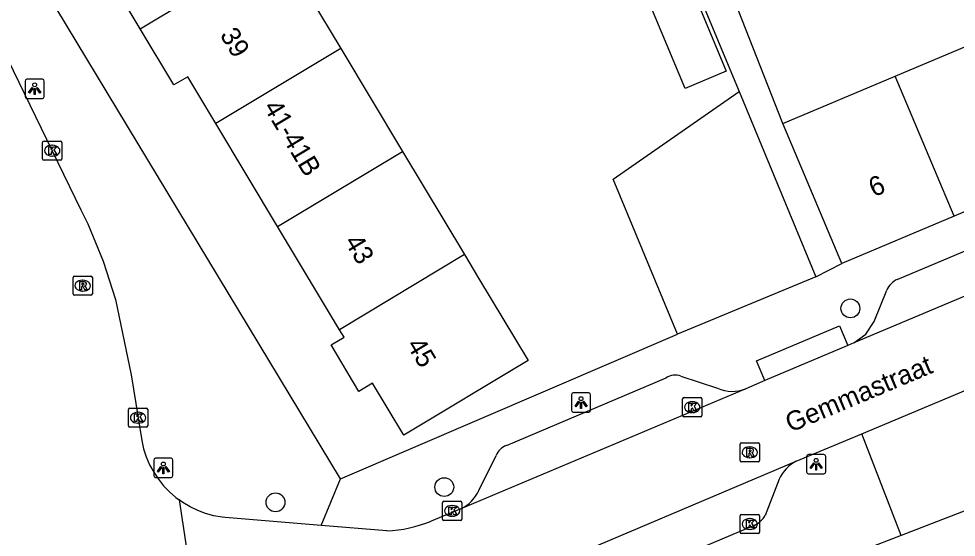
# Model space of a CAD drawing. Extents: x 159888 to 160757, y 384031 to 384746.
# Drawn here: x 160361.8 to 160410.46, y 384537.67 to 384564.6 of the extents above; entities that cross this region are included whole.
import ezdxf

# ---------------------------------------------------------------- set-up
doc = ezdxf.new("R2010")
doc.units = 0
for name, color, linetype in [('IMGEO_Boom', 7, 'Continuous'), ('IMGEO_Kolk', 7, 'Continuous'), ('IMGEO_Lichtpunt', 7, 'Continuous'), ('IMGEO_Muur', 7, 'Continuous'), ('IMGEO_Openbare_ruimte_label', 7, 'Continuous'), ('IMGEO_Pand', 7, 'Continuous'), ('IMGEO_Pand_nummerreeks', 7, 'Continuous'), ('IMGEO_Rijbaan_lokaal_open', 7, 'Continuous'), ('IMGEO_Rioolput', 7, 'Continuous'), ('IMGEO_Voetpad_open', 7, 'Continuous')]:
    doc.layers.add(name, color=color, linetype=linetype)

msp = doc.modelspace()

# ---------------------------------------------------------------- linework, layer by layer
at = {"layer": 'IMGEO_Boom'}
for centre in [(160404.965, 384549.558), (160383.887, 384540.276), (160375.125, 384539.485)]:
    msp.add_circle(centre, 0.489, dxfattribs=at)
at = {"layer": 'IMGEO_Kolk'}
for p, q in [((160363.037, 384557.325), (160363.037, 384558.177)), ((160363.112, 384558.251), (160363.964, 384558.251)), ((160363.525, 384558.031), (160363.55, 384558.031)), ((160364.038, 384558.177), (160364.038, 384557.325)), ((160363.548, 384557.471), (160363.523, 384557.471)), ((160363.964, 384557.251), (160363.112, 384557.251)), ((160396.257, 384544.002), (160396.257, 384544.854)), ((160396.332, 384544.928), (160397.184, 384544.928)), ((160396.745, 384544.708), (160396.77, 384544.708)), ((160397.258, 384544.854), (160397.258, 384544.002)), ((160367.494, 384543.455), (160367.494, 384544.307)), ((160367.569, 384544.381), (160368.421, 384544.381)), ((160367.982, 384544.161), (160368.007, 384544.161)), ((160368.495, 384544.307), (160368.495, 384543.455)), ((160397.184, 384543.928), (160396.332, 384543.928)), ((160396.768, 384544.148), (160396.743, 384544.148)), ((160368.421, 384543.381), (160367.569, 384543.381)), ((160368.005, 384543.601), (160367.98, 384543.601)), ((160383.796, 384538.612), (160383.796, 384539.464)), ((160383.871, 384539.538), (160384.723, 384539.538)), ((160384.284, 384539.318), (160384.309, 384539.318)), ((160384.797, 384539.464), (160384.797, 384538.612)), ((160399.32, 384538.858), (160400.172, 384538.858)), ((160384.723, 384538.538), (160383.871, 384538.538)), ((160384.307, 384538.758), (160384.282, 384538.758)), ((160399.245, 384537.932), (160399.245, 384538.784)), ((160399.733, 384538.638), (160399.758, 384538.638)), ((160400.246, 384538.784), (160400.246, 384537.932)), ((160400.172, 384537.858), (160399.32, 384537.858)), ((160399.756, 384538.078), (160399.731, 384538.078))]:
    msp.add_line(p, q, dxfattribs=at)
for points in [[(160363.037, 384557.325), (160363.037, 384558.177)], [(160363.112, 384558.251), (160363.964, 384558.251)], [(160363.358, 384557.951), (160363.481, 384557.951), (160363.481, 384557.8), (160363.611, 384557.951), (160363.775, 384557.951), (160363.629, 384557.8), (160363.782, 384557.551), (160363.63, 384557.551), (160363.545, 384557.715), (160363.481, 384557.648), (160363.481, 384557.551), (160363.358, 384557.551), (160363.358, 384557.951)], [(160364.038, 384558.177), (160364.038, 384557.325)], [(160363.964, 384557.251), (160363.112, 384557.251)], [(160396.257, 384544.002), (160396.257, 384544.854)], [(160396.332, 384544.928), (160397.184, 384544.928)], [(160397.258, 384544.854), (160397.258, 384544.002)], [(160367.494, 384543.455), (160367.494, 384544.307)], [(160367.569, 384544.381), (160368.421, 384544.381)], [(160368.495, 384544.307), (160368.495, 384543.455)], [(160396.578, 384544.628), (160396.701, 384544.628), (160396.701, 384544.477), (160396.831, 384544.628), (160396.995, 384544.628), (160396.849, 384544.477), (160397.002, 384544.228), (160396.85, 384544.228), (160396.765, 384544.392), (160396.701, 384544.325), (160396.701, 384544.228), (160396.578, 384544.228), (160396.578, 384544.628)], [(160367.815, 384544.081), (160367.938, 384544.081), (160367.938, 384543.93), (160368.068, 384544.081), (160368.232, 384544.081), (160368.086, 384543.93), (160368.239, 384543.681), (160368.087, 384543.681), (160368.002, 384543.845), (160367.938, 384543.778), (160367.938, 384543.681), (160367.815, 384543.681), (160367.815, 384544.081)], [(160397.184, 384543.928), (160396.332, 384543.928)], [(160368.421, 384543.381), (160367.569, 384543.381)], [(160383.796, 384538.612), (160383.796, 384539.464)], [(160383.871, 384539.538), (160384.723, 384539.538)], [(160384.797, 384539.464), (160384.797, 384538.612)], [(160384.117, 384539.238), (160384.24, 384539.238), (160384.24, 384539.087), (160384.37, 384539.238), (160384.534, 384539.238), (160384.388, 384539.087), (160384.541, 384538.838), (160384.389, 384538.838), (160384.304, 384539.002), (160384.24, 384538.935), (160384.24, 384538.838), (160384.117, 384538.838), (160384.117, 384539.238)], [(160399.32, 384538.858), (160400.172, 384538.858)], [(160384.723, 384538.538), (160383.871, 384538.538)], [(160399.245, 384537.932), (160399.245, 384538.784)], [(160399.566, 384538.558), (160399.689, 384538.558), (160399.689, 384538.407), (160399.819, 384538.558), (160399.983, 384538.558), (160399.837, 384538.407), (160399.99, 384538.158), (160399.838, 384538.158), (160399.753, 384538.322), (160399.689, 384538.255), (160399.689, 384538.158), (160399.566, 384538.158), (160399.566, 384538.558)], [(160400.246, 384538.784), (160400.246, 384537.932)], [(160400.172, 384537.858), (160399.32, 384537.858)]]:
    msp.add_lwpolyline(points, dxfattribs=at)
for centre, start, end in [((160363.114, 384558.175), 91.552, 178.448), ((160363.114, 384558.175), 91.552, 178.448), ((160363.962, 384558.175), 1.552, 88.448), ((160363.962, 384558.175), 1.552, 88.448), ((160363.114, 384557.327), 181.552, 268.448), ((160363.114, 384557.327), 181.552, 268.448), ((160363.962, 384557.327), 271.552, 358.448), ((160363.962, 384557.327), 271.552, 358.448), ((160396.334, 384544.852), 91.552, 178.448), ((160396.334, 384544.852), 91.552, 178.448), ((160397.182, 384544.852), 1.552, 88.448), ((160397.182, 384544.852), 1.552, 88.448), ((160367.571, 384544.305), 91.552, 178.448), ((160367.571, 384544.305), 91.552, 178.448), ((160368.419, 384544.305), 1.552, 88.448), ((160368.419, 384544.305), 1.552, 88.448), ((160396.334, 384544.004), 181.552, 268.448), ((160396.334, 384544.004), 181.552, 268.448), ((160397.182, 384544.004), 271.552, 358.448), ((160397.182, 384544.004), 271.552, 358.448), ((160367.571, 384543.457), 181.552, 268.448), ((160367.571, 384543.457), 181.552, 268.448), ((160368.419, 384543.457), 271.552, 358.448), ((160368.419, 384543.457), 271.552, 358.448), ((160383.873, 384539.462), 91.552, 178.448), ((160383.873, 384539.462), 91.552, 178.448), ((160384.721, 384539.462), 1.552, 88.448), ((160384.721, 384539.462), 1.552, 88.448), ((160399.322, 384538.782), 91.552, 178.448), ((160399.322, 384538.782), 91.552, 178.448), ((160400.17, 384538.782), 1.552, 88.448), ((160400.17, 384538.782), 1.552, 88.448), ((160383.873, 384538.614), 181.552, 268.448), ((160383.873, 384538.614), 181.552, 268.448), ((160384.721, 384538.614), 271.552, 358.448), ((160384.721, 384538.614), 271.552, 358.448), ((160399.322, 384537.934), 181.552, 268.448), ((160399.322, 384537.934), 181.552, 268.448), ((160400.17, 384537.934), 271.552, 358.448), ((160400.17, 384537.934), 271.552, 358.448)]:
    msp.add_arc(centre, 0.0765, start, end, dxfattribs=at)
for centre, major_axis, ratio, start_param, end_param in [((160363.524, 384557.751), (-0.387, 0.002), 0.722429, 4.712389, 7.853982), ((160363.549, 384557.751), (-0.39, 0.002), 0.717154, 1.570796, 4.712389), ((160396.744, 384544.428), (-0.387, 0.002), 0.722429, 4.712389, 7.853982), ((160396.769, 384544.428), (-0.39, 0.002), 0.717154, 1.570796, 4.712389), ((160367.981, 384543.881), (-0.387, 0.002), 0.722429, 4.712389, 7.853982), ((160368.006, 384543.881), (-0.39, 0.002), 0.717154, 1.570796, 4.712389), ((160384.283, 384539.038), (-0.387, 0.002), 0.722429, 4.712389, 7.853982), ((160384.308, 384539.038), (-0.39, 0.002), 0.717154, 1.570796, 4.712389), ((160399.732, 384538.358), (-0.387, 0.002), 0.722429, 4.712389, 7.853982), ((160399.757, 384538.358), (-0.39, 0.002), 0.717154, 1.570796, 4.712389)]:
    msp.add_ellipse(centre, major_axis=major_axis, ratio=ratio, start_param=start_param, end_param=end_param, dxfattribs=at)
at = {"layer": 'IMGEO_Lichtpunt'}
for p, q in [((160362.129, 384561.369), (160362.129, 384560.562)), ((160362.129, 384561.369), (160362.129, 384560.562)), ((160363.031, 384561.464), (160362.223, 384561.464)), ((160363.031, 384561.464), (160362.223, 384561.464)), ((160363.125, 384560.562), (160363.125, 384561.369)), ((160363.125, 384560.562), (160363.125, 384561.369)), ((160362.223, 384560.468), (160363.031, 384560.468)), ((160362.223, 384560.468), (160363.031, 384560.468)), ((160391.389, 384545.166), (160390.581, 384545.166)), ((160391.389, 384545.166), (160390.581, 384545.166)), ((160390.487, 384545.071), (160390.487, 384544.264)), ((160390.487, 384545.071), (160390.487, 384544.264)), ((160391.483, 384544.264), (160391.483, 384545.071)), ((160391.483, 384544.264), (160391.483, 384545.071)), ((160390.581, 384544.17), (160391.389, 384544.17)), ((160390.581, 384544.17), (160391.389, 384544.17)), ((160369.71, 384541.774), (160368.902, 384541.774)), ((160369.71, 384541.774), (160368.902, 384541.774)), ((160402.69, 384541.868), (160402.69, 384541.061)), ((160402.69, 384541.868), (160402.69, 384541.061)), ((160403.592, 384541.963), (160402.784, 384541.963)), ((160403.592, 384541.963), (160402.784, 384541.963)), ((160403.686, 384541.061), (160403.686, 384541.868)), ((160403.686, 384541.061), (160403.686, 384541.868)), ((160368.808, 384541.679), (160368.808, 384540.872)), ((160368.808, 384541.679), (160368.808, 384540.872)), ((160369.804, 384540.872), (160369.804, 384541.679)), ((160369.804, 384540.872), (160369.804, 384541.679)), ((160368.902, 384540.778), (160369.71, 384540.778)), ((160368.902, 384540.778), (160369.71, 384540.778)), ((160402.784, 384540.967), (160403.592, 384540.967)), ((160402.784, 384540.967), (160403.592, 384540.967))]:
    msp.add_line(p, q, dxfattribs=at)
for points in [[(160362.503, 384561.033), (160362.542, 384561.005), (160362.354, 384560.743), (160362.316, 384560.77), (160362.503, 384561.033)], [(160362.605, 384560.985), (160362.652, 384560.985), (160362.652, 384560.663), (160362.605, 384560.663), (160362.605, 384560.985)], [(160362.715, 384561.005), (160362.753, 384561.032), (160362.94, 384560.77), (160362.901, 384560.742), (160362.715, 384561.005)], [(160390.861, 384544.735), (160390.9, 384544.707), (160390.712, 384544.445), (160390.674, 384544.472), (160390.861, 384544.735)], [(160390.963, 384544.687), (160391.01, 384544.687), (160391.01, 384544.365), (160390.963, 384544.365), (160390.963, 384544.687)], [(160391.073, 384544.707), (160391.111, 384544.734), (160391.298, 384544.472), (160391.259, 384544.444), (160391.073, 384544.707)], [(160369.182, 384541.343), (160369.221, 384541.315), (160369.033, 384541.053), (160368.995, 384541.08), (160369.182, 384541.343)], [(160369.284, 384541.295), (160369.331, 384541.295), (160369.331, 384540.973), (160369.284, 384540.973), (160369.284, 384541.295)], [(160369.394, 384541.315), (160369.432, 384541.342), (160369.619, 384541.08), (160369.58, 384541.052), (160369.394, 384541.315)], [(160403.064, 384541.532), (160403.103, 384541.504), (160402.915, 384541.242), (160402.877, 384541.269), (160403.064, 384541.532)], [(160403.166, 384541.484), (160403.213, 384541.484), (160403.213, 384541.162), (160403.166, 384541.162), (160403.166, 384541.484)], [(160403.276, 384541.504), (160403.314, 384541.531), (160403.501, 384541.269), (160403.462, 384541.241), (160403.276, 384541.504)]]:
    msp.add_lwpolyline(points, dxfattribs=at)
for centre in [(160362.628, 384561.167), (160390.986, 384544.869), (160403.189, 384541.666), (160369.307, 384541.477)]:
    msp.add_circle(centre, 0.0994, dxfattribs=at)
for centre, start, end in [((160362.223, 384561.369), 90, 180), ((160362.223, 384561.369), 90, 180), ((160363.031, 384561.369), 0, 90), ((160363.031, 384561.369), 0, 90), ((160362.223, 384560.562), 180, 270), ((160362.223, 384560.562), 180, 270), ((160363.031, 384560.562), 270, 0), ((160363.031, 384560.562), 270, 360), ((160390.581, 384545.071), 90, 180), ((160390.581, 384545.071), 90, 180), ((160391.389, 384545.071), 0, 90), ((160391.389, 384545.071), 0, 90), ((160390.581, 384544.264), 180, 270), ((160390.581, 384544.264), 180, 270), ((160391.389, 384544.264), 270, 0), ((160391.389, 384544.264), 270, 360), ((160368.902, 384541.679), 90, 180), ((160368.902, 384541.679), 90, 180), ((160369.71, 384541.679), 0, 90), ((160369.71, 384541.679), 0, 90), ((160402.784, 384541.868), 90, 180), ((160402.784, 384541.868), 90, 180), ((160403.592, 384541.868), 0, 90), ((160403.592, 384541.868), 0, 90), ((160368.902, 384540.872), 180, 270), ((160368.902, 384540.872), 180, 270), ((160369.71, 384540.872), 270, 0), ((160369.71, 384540.872), 270, 360), ((160402.784, 384541.061), 180, 270), ((160402.784, 384541.061), 180, 270), ((160403.592, 384541.061), 270, 0), ((160403.592, 384541.061), 270, 360)]:
    msp.add_arc(centre, 0.0946, start, end, dxfattribs=at)
at = {"layer": 'IMGEO_Muur'}
msp.add_lwpolyline([(160389.27, 384545.328), (160395.985, 384548.227)], dxfattribs=at)
at = {"layer": 'IMGEO_Pand'}
for points in [[(160368.103, 384564.081), (160366.562, 384566.651), (160367.264, 384567.072), (160365.594, 384569.857)], [(160368.103, 384564.081), (160375.308, 384568.416)], [(160375.308, 384568.416), (160378.518, 384563.062)], [(160396.661, 384566.35), (160398.525, 384561.872), (160396.387, 384560.982), (160394.53, 384565.442)], [(160372.028, 384559.158), (160370.569, 384561.592), (160369.853, 384561.163), (160368.103, 384564.081)], [(160407.283, 384561.617), (160412.991, 384564.023)], [(160378.518, 384563.062), (160372.028, 384559.158)], [(160378.518, 384563.062), (160381.727, 384557.71)], [(160401.465, 384559.165), (160407.283, 384561.617)], [(160410.349, 384554.348), (160407.283, 384561.617)], [(160395.985, 384548.227), (160392.659, 384556.266), (160399.191, 384560.83)], [(160399.191, 384560.83), (160403.174, 384551.201)], [(160375.237, 384553.806), (160372.028, 384559.158)], [(160404.529, 384551.895), (160402.587, 384556.503), (160401.465, 384559.165)], [(160375.237, 384553.806), (160381.727, 384557.71)], [(160381.727, 384557.71), (160384.938, 384552.356)], [(160416.055, 384556.752), (160410.349, 384554.348)], [(160410.349, 384554.348), (160404.529, 384551.895)], [(160378.448, 384548.452), (160375.237, 384553.806)], [(160384.938, 384552.356), (160385.671, 384551.133), (160388.243, 384546.844), (160381.785, 384542.971), (160380.168, 384545.667), (160379.461, 384545.243), (160378.014, 384547.658), (160378.683, 384548.059), (160378.448, 384548.452)], [(160384.938, 384552.356), (160378.448, 384548.452)], [(160403.174, 384551.201), (160395.985, 384548.227)]]:
    msp.add_lwpolyline(points, dxfattribs=at)
at = {"layer": 'IMGEO_Rijbaan_lokaal_open'}
for points in [[(160339.964, 384598.8), (160340.324, 384598.252), (160348.814, 384584.217), (160353.575, 384576.372), (160357.819, 384569.337), (160358.601, 384567.882), (160363.537, 384557.75), (160365.031, 384554.673), (160365.385, 384553.953), (160366.191, 384552.018), (160366.821, 384550.019), (160367.631, 384546.105), (160367.993, 384543.881), (160368.184, 384542.689), (160368.283, 384542.26), (160368.42, 384541.843), (160368.594, 384541.439), (160368.804, 384541.052), (160369.047, 384540.685), (160369.322, 384540.342), (160369.626, 384540.024), (160369.958, 384539.735), (160370.13, 384539.61)], [(160420.485, 384554.23), (160405.149, 384547.777)], [(160404.838, 384547.639), (160400.53, 384545.818)], [(160405.149, 384547.777), (160404.838, 384547.639)], [(160405.552, 384543.044), (160413.022, 384546.183)], [(160400.53, 384545.818), (160399.539, 384545.383)], [(160399.539, 384545.383), (160384.75, 384539.152)], [(160402.155, 384541.617), (160405.552, 384543.044)], [(160391.337, 384537.036), (160402.155, 384541.617)], [(160377.501, 384538.278), (160372.516, 384538.691), (160372.356, 384538.71), (160371.924, 384538.789), (160371.5, 384538.906), (160371.088, 384539.061), (160370.691, 384539.252), (160370.314, 384539.477), (160370.13, 384539.61)], [(160370.13, 384539.61), (160371.488, 384530.538)], [(160384.75, 384539.152), (160383.212, 384538.508)], [(160380.904, 384537.996), (160377.501, 384538.278)]]:
    msp.add_lwpolyline(points, dxfattribs=at)
msp.add_arc((160380.529, 384545.145), 7.158, 273.0031, 292.0124, dxfattribs=at)
at = {"layer": 'IMGEO_Rioolput'}
for p, q in [((160364.62, 384550.313), (160364.62, 384551.165)), ((160364.695, 384551.239), (160365.547, 384551.239)), ((160365.108, 384551.019), (160365.133, 384551.019)), ((160365.621, 384551.165), (160365.621, 384550.313)), ((160365.547, 384550.239), (160364.695, 384550.239)), ((160365.131, 384550.459), (160365.106, 384550.459)), ((160399.244, 384541.656), (160399.244, 384542.508)), ((160399.319, 384542.582), (160400.171, 384542.582)), ((160399.732, 384542.362), (160399.757, 384542.362)), ((160400.245, 384542.508), (160400.245, 384541.656)), ((160399.755, 384541.802), (160399.73, 384541.802)), ((160400.171, 384541.582), (160399.319, 384541.582))]:
    msp.add_line(p, q, dxfattribs=at)
for points in [[(160364.62, 384550.313), (160364.62, 384551.165)], [(160364.695, 384551.239), (160365.547, 384551.239)], [(160365.621, 384551.165), (160365.621, 384550.313)], [(160365.209, 384550.937), (160364.957, 384550.939), (160364.957, 384550.539)], [(160364.957, 384550.539), (160365.081, 384550.539), (160365.081, 384550.701), (160365.092, 384550.701)], [(160365.135, 384550.858), (160365.081, 384550.858), (160365.081, 384550.777)], [(160365.081, 384550.777), (160365.133, 384550.777)], [(160365.139, 384550.672), (160365.21, 384550.539), (160365.35, 384550.539), (160365.285, 384550.665)], [(160365.547, 384550.239), (160364.695, 384550.239)], [(160399.244, 384541.656), (160399.244, 384542.508)], [(160399.319, 384542.582), (160400.171, 384542.582)], [(160399.833, 384542.28), (160399.581, 384542.282), (160399.581, 384541.882)], [(160400.245, 384542.508), (160400.245, 384541.656)], [(160399.581, 384541.882), (160399.705, 384541.882), (160399.705, 384542.044), (160399.716, 384542.044)], [(160399.759, 384542.201), (160399.705, 384542.201), (160399.705, 384542.12)], [(160399.705, 384542.12), (160399.757, 384542.12)], [(160399.763, 384542.015), (160399.834, 384541.882), (160399.974, 384541.882), (160399.909, 384542.008)], [(160400.171, 384541.582), (160399.319, 384541.582)]]:
    msp.add_lwpolyline(points, dxfattribs=at)
for centre, radius, start, end in [((160364.697, 384551.163), 0.0765, 91.552, 178.448), ((160364.697, 384551.163), 0.0765, 91.552, 178.448), ((160365.545, 384551.163), 0.0765, 1.552, 88.448), ((160365.545, 384551.163), 0.0765, 1.552, 88.448), ((160365.091, 384550.648), 0.0533, 26.0293, 88.6989), ((160365.117, 384550.966), 0.19, 274.7715, 282.9687), ((160365.141, 384550.762), 0.0964, 77.0061, 93.1865), ((160365.155, 384550.819), 0.0378, 276.6634, 79.6772), ((160365.208, 384550.827), 0.109, 350.3612, 89.416), ((160365.206, 384550.827), 0.112, 277.5842, 350.9817), ((160365.19, 384550.612), 0.108, 29.5134, 73.7905), ((160364.697, 384550.315), 0.0765, 181.552, 268.448), ((160364.697, 384550.315), 0.0765, 181.552, 268.448), ((160365.545, 384550.315), 0.0765, 271.552, 358.448), ((160365.545, 384550.315), 0.0765, 271.552, 358.448), ((160399.321, 384542.506), 0.0765, 91.552, 178.448), ((160399.321, 384542.506), 0.0765, 91.552, 178.448), ((160399.832, 384542.17), 0.109, 350.3612, 89.416), ((160400.169, 384542.506), 0.0765, 1.552, 88.448), ((160400.169, 384542.506), 0.0765, 1.552, 88.448), ((160399.715, 384541.991), 0.0533, 26.0293, 88.6989), ((160399.741, 384542.309), 0.19, 274.7715, 282.9687), ((160399.765, 384542.105), 0.0964, 77.0061, 93.1865), ((160399.779, 384542.162), 0.0378, 276.6634, 79.6772), ((160399.83, 384542.17), 0.112, 277.5842, 350.9817), ((160399.814, 384541.955), 0.108, 29.5134, 73.7905), ((160399.321, 384541.658), 0.0765, 181.552, 268.448), ((160399.321, 384541.658), 0.0765, 181.552, 268.448), ((160400.169, 384541.658), 0.0765, 271.552, 358.448), ((160400.169, 384541.658), 0.0765, 271.552, 358.448)]:
    msp.add_arc(centre, radius, start, end, dxfattribs=at)
for centre, major_axis, ratio, start_param, end_param in [((160365.107, 384550.739), (-0.387, 0.002), 0.722429, 4.712389, 7.853982), ((160365.132, 384550.739), (-0.39, 0.002), 0.717154, 1.570796, 4.712389), ((160399.731, 384542.082), (-0.387, 0.002), 0.722429, 4.712389, 7.853982), ((160399.756, 384542.082), (-0.39, 0.002), 0.717154, 1.570796, 4.712389)]:
    msp.add_ellipse(centre, major_axis=major_axis, ratio=ratio, start_param=start_param, end_param=end_param, dxfattribs=at)
at = {"layer": 'IMGEO_Voetpad_open'}
for points in [[(160378.5, 384540.702), (160327.382, 384625.41), (160326.591, 384626.72)], [(160393.759, 384573.881), (160399.191, 384560.83)], [(160401.465, 384559.165), (160399.143, 384565.06)], [(160407.394, 384551.064), (160416.63, 384554.96)], [(160403.174, 384551.201), (160404.529, 384551.895)], [(160405.149, 384547.777), (160405.771, 384548.215), (160406.195, 384548.88), (160406.854, 384550.51)], [(160400.53, 384545.818), (160400.099, 384546.834), (160404.402, 384548.644), (160404.838, 384547.639)], [(160378.5, 384540.702), (160389.27, 384545.328), (160395.985, 384548.227)], [(160387.111, 384542.442), (160395.401, 384545.955)], [(160396.17, 384546.038), (160398.067, 384545.409)], [(160407.602, 384537.77), (160405.552, 384543.044)], [(160385.682, 384540.106), (160386.577, 384541.911)], [(160377.501, 384538.278), (160378.5, 384540.702)], [(160401.263, 384540.681), (160400.547, 384538.807)], [(160415.244, 384540.729), (160407.602, 384537.77)], [(160399.978, 384538.288), (160395.386, 384536.334)], [(160407.602, 384537.77), (160403.821, 384536.302), (160403.542, 384536.194), (160403.465, 384536.272), (160397.147, 384533.607), (160392.687, 384530.416), (160389.463, 384528.155)]]:
    msp.add_lwpolyline(points, dxfattribs=at)
for centre, radius, start, end in [((160407.88, 384550.05), 1.125, 115.6222, 155.8441), ((160395.867, 384545.243), 0.851, 69.1213, 123.1992), ((160398.834, 384547.139), 1.892, 246.0979, 291.8783), ((160387.422, 384541.596), 0.902, 110.1571, 159.5201), ((160403.022, 384539.898), 1.926, 116.7631, 155.9946), ((160383.869, 384540.945), 1.998, 296.1725, 335.1641), ((160399.472, 384539.414), 1.235, 294.1964, 330.5411)]:
    msp.add_arc(centre, radius, start, end, dxfattribs=at)

# ---------------------------------------------------------------- texts
at = {"layer": 'IMGEO_Openbare_ruimte_label'}
msp.add_text('Gemmastraat', height=1, rotation=22.8225, dxfattribs=at).set_placement((160401.854, 384543.101))
at = {"layer": 'IMGEO_Pand_nummerreeks'}
for s, rotation, p in [('39', 301.0302, (160372.218, 384563.764)), ('41-41B', 301.0302, (160374.474, 384560.015)), ('6', 22.8514, (160406.179, 384555.325)), ('43', 301.0302, (160378.676, 384553.029)), ('45', 301.0302, (160381.905, 384547.662))]:
    msp.add_text(s, height=1, rotation=rotation, dxfattribs=at).set_placement(p)

doc.saveas('drawing.dxf')
